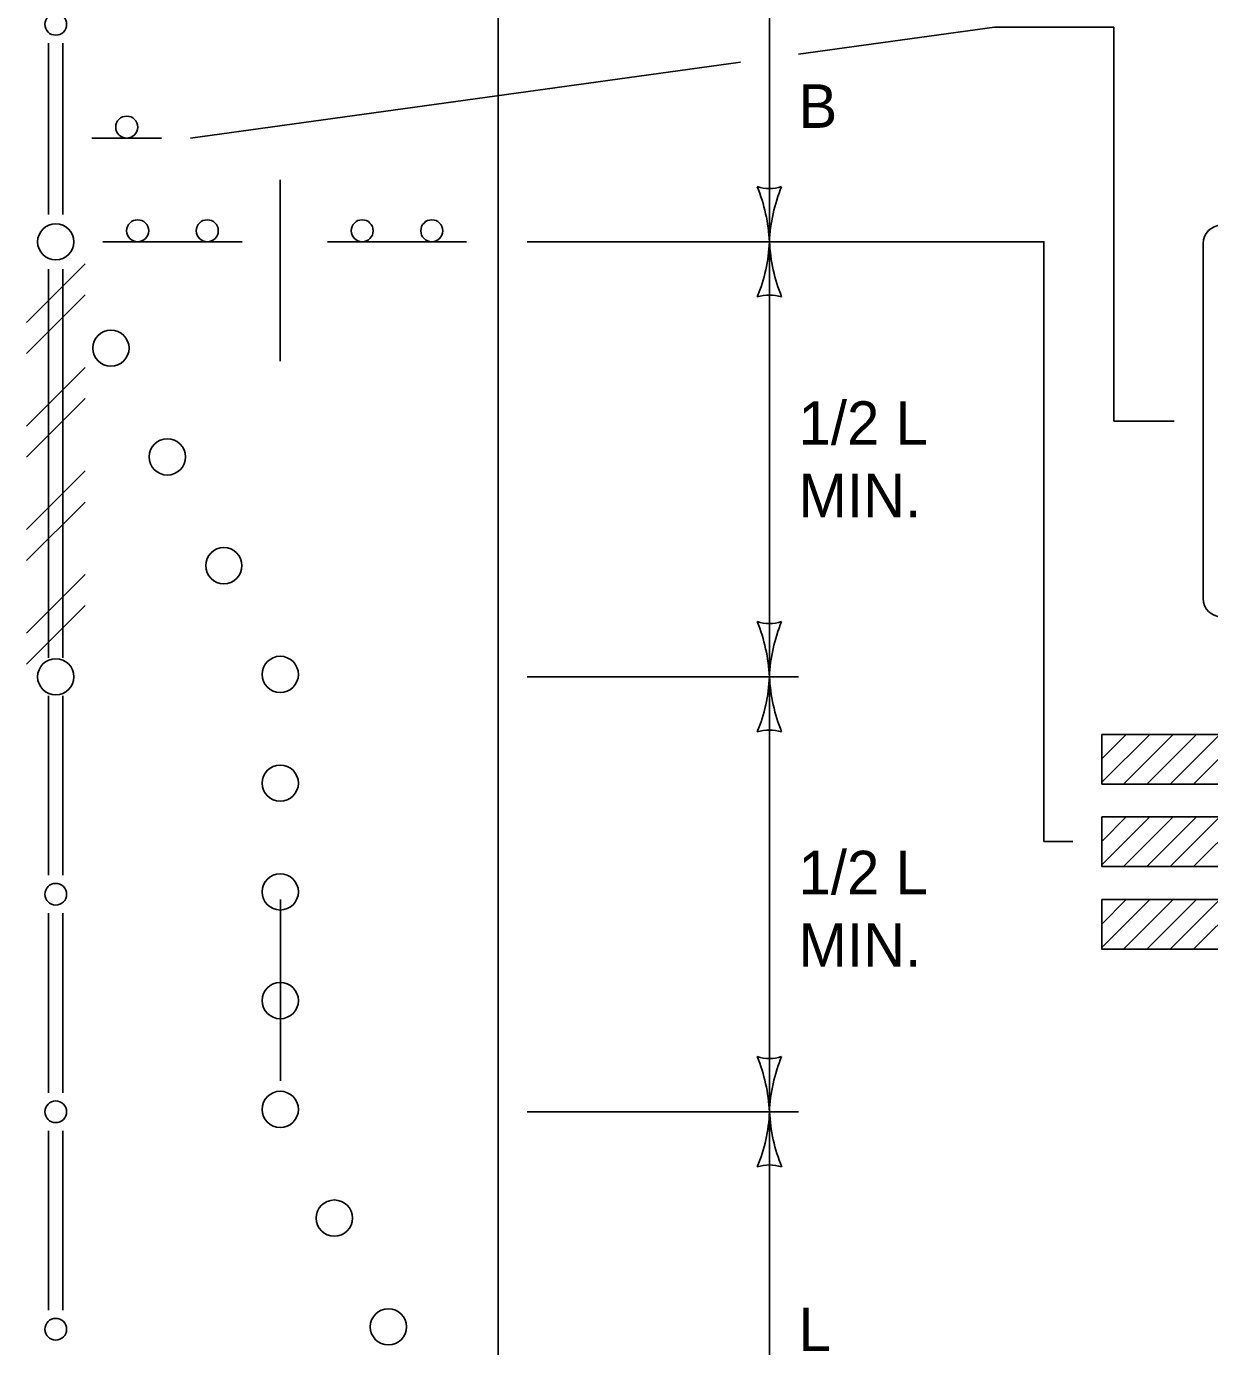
# Model space of a CAD drawing. Extents: x 49991.4 to 50021, y 49987.6 to 50011.4.
# Drawn here: x 50010.553 to 50012.184, y 49990.574 to 49992.395 of the extents above; entities that cross this region are included whole.
import ezdxf

# ---------------------------------------------------------------- set-up
doc = ezdxf.new("R2010")
doc.units = 0
for name, color, linetype in [('Level 1', 7, 'Continuous'), ('Level 2', 7, 'Continuous'), ('Level 3', 7, 'Continuous')]:
    doc.layers.add(name, color=color, linetype=linetype)

# ---------------------------------------------------------------- blocks, each defined once
blk = doc.blocks.new('ARR')
at = {"layer": 'Level 3'}
for centre, radius, start, end in [((1.53, 37.02), 37.05, 247.456, 267.6395), ((-21.37, 0), 9.13, 342.1388, 17.8612), ((1.92, -38.79), 38.83, 92.8273, 112.0772)]:
    blk.add_arc(centre, radius, start, end, dxfattribs=at)

msp = doc.modelspace()

# ---------------------------------------------------------------- linework, layer by layer
at = {"layer": 'Level 1'}
for p, q in [((50011.2032, 49988.1586), (50011.2032, 49992.9404)), ((50010.5832, 49992.1356), (50010.5832, 49992.3715)), ((50010.6032, 49992.1356), (50010.6032, 49992.3715)), ((50010.7392, 49992.2408), (50010.6432, 49992.2408)), ((50010.9028, 49991.9331), (50010.9028, 49992.1831)), ((50010.5682, 49992.0977), (50010.5682, 49992.0977)), ((50010.6582, 49992.0977), (50010.7542, 49992.0977)), ((50010.7542, 49992.0977), (50010.8502, 49992.0977)), ((50010.9678, 49992.0977), (50011.0638, 49992.0977)), ((50011.0638, 49992.0977), (50011.1598, 49992.0977)), ((50012.1754, 49991.6058), (50012.1754, 49992.0952)), ((50010.5528, 49991.9865), (50010.6336, 49992.0673)), ((50010.5832, 49991.5239), (50010.5832, 49992.0598)), ((50010.6032, 49991.5239), (50010.6032, 49992.0598)), ((50010.5528, 49991.9436), (50010.6336, 49992.0244)), ((50010.6443, 49991.951), (50010.6443, 49991.951)), ((50010.5528, 49991.8436), (50010.6336, 49991.9244)), ((50010.5528, 49991.8008), (50010.6336, 49991.8816)), ((50010.7222, 49991.801), (50010.7222, 49991.801)), ((50010.5528, 49991.7008), (50010.6336, 49991.7816)), ((50010.5528, 49991.6579), (50010.6336, 49991.7387)), ((50010.5528, 49991.5579), (50010.6336, 49991.6387)), ((50010.8, 49991.651), (50010.8, 49991.651)), ((50010.5528, 49991.5151), (50010.6336, 49991.5959)), ((50010.5682, 49991.4977), (50010.5682, 49991.4977)), ((50010.8778, 49991.501), (50010.8778, 49991.501)), ((50010.5832, 49991.2239), (50010.5832, 49991.4715)), ((50010.6032, 49991.2239), (50010.6032, 49991.4715)), ((50012.0359, 49991.3524), (50012.1018, 49991.4182)), ((50012.0359, 49991.3846), (50012.0695, 49991.4182)), ((50012.0695, 49991.4182), (50012.0359, 49991.3846)), ((50012.0359, 49991.3524), (50012.1018, 49991.4182)), ((50012.0656, 49991.3498), (50012.134, 49991.4182)), ((50012.134, 49991.4182), (50012.0656, 49991.3498)), ((50012.0978, 49991.3498), (50012.1662, 49991.4182)), ((50012.0978, 49991.3498), (50012.1662, 49991.4182)), ((50012.1301, 49991.3498), (50012.1985, 49991.4182)), ((50012.1985, 49991.4182), (50012.1301, 49991.3498)), ((50012.1623, 49991.3498), (50012.2307, 49991.4182)), ((50012.1623, 49991.3498), (50012.2307, 49991.4182)), ((50010.8778, 49991.351), (50010.8778, 49991.351)), ((50012.0359, 49991.2384), (50012.1018, 49991.3043)), ((50012.0359, 49991.2706), (50012.0695, 49991.3043)), ((50012.0695, 49991.3043), (50012.0359, 49991.2706)), ((50012.0359, 49991.2384), (50012.1018, 49991.3043)), ((50012.0656, 49991.2359), (50012.134, 49991.3043)), ((50012.134, 49991.3043), (50012.0656, 49991.2359)), ((50012.0978, 49991.2359), (50012.1662, 49991.3043)), ((50012.0978, 49991.2359), (50012.1662, 49991.3043)), ((50012.1301, 49991.2359), (50012.1985, 49991.3043)), ((50012.1985, 49991.3043), (50012.1301, 49991.2359)), ((50012.1623, 49991.2359), (50012.2307, 49991.3043)), ((50012.1623, 49991.2359), (50012.2307, 49991.3043)), ((50010.8778, 49991.201), (50010.8778, 49991.201)), ((50010.9033, 49990.9404), (50010.9033, 49991.1904)), ((50012.0359, 49991.1244), (50012.1018, 49991.1903)), ((50012.0359, 49991.1567), (50012.0695, 49991.1903)), ((50012.0695, 49991.1903), (50012.0359, 49991.1567)), ((50012.0359, 49991.1244), (50012.1018, 49991.1903)), ((50012.0656, 49991.1219), (50012.134, 49991.1903)), ((50012.134, 49991.1903), (50012.0656, 49991.1219)), ((50012.0978, 49991.1219), (50012.1662, 49991.1903)), ((50012.0978, 49991.1219), (50012.1662, 49991.1903)), ((50012.1301, 49991.1219), (50012.1985, 49991.1903)), ((50012.1985, 49991.1903), (50012.1301, 49991.1219)), ((50012.1623, 49991.1219), (50012.2307, 49991.1903)), ((50012.1623, 49991.1219), (50012.2307, 49991.1903)), ((50010.5832, 49990.9239), (50010.5832, 49991.1715)), ((50010.6032, 49990.9239), (50010.6032, 49991.1715)), ((50010.8778, 49991.051), (50010.8778, 49991.051)), ((50010.8778, 49990.901), (50010.8778, 49990.901)), ((50010.5832, 49990.6239), (50010.5832, 49990.8715)), ((50010.6032, 49990.6239), (50010.6032, 49990.8715))]:
    msp.add_line(p, q, dxfattribs=at)
for points in [[(50012.5147, 49991.3498), (50012.0359, 49991.3498), (50012.0359, 49991.4182), (50012.2411, 49991.4182)], [(50012.1018, 49991.4182), (50012.0695, 49991.4182)], [(50012.1662, 49991.4182), (50012.134, 49991.4182)], [(50012.0359, 49991.3846), (50012.0359, 49991.3524)], [(50012.0656, 49991.3498), (50012.0978, 49991.3498)], [(50012.1301, 49991.3498), (50012.1623, 49991.3498)], [(50012.5147, 49991.3043), (50012.7199, 49991.3043), (50012.7199, 49991.2359), (50012.0359, 49991.2359), (50012.0359, 49991.3043), (50012.5147, 49991.3043)], [(50012.1018, 49991.3043), (50012.0695, 49991.3043)], [(50012.1662, 49991.3043), (50012.134, 49991.3043)], [(50012.0359, 49991.2706), (50012.0359, 49991.2384)], [(50012.0656, 49991.2359), (50012.0978, 49991.2359)], [(50012.1301, 49991.2359), (50012.1623, 49991.2359)], [(50012.5531, 49991.1903), (50012.7199, 49991.1903), (50012.7199, 49991.1219), (50012.0359, 49991.1219), (50012.0359, 49991.1903), (50012.1985, 49991.1903)], [(50012.1018, 49991.1903), (50012.0695, 49991.1903)], [(50012.1662, 49991.1903), (50012.134, 49991.1903)], [(50012.0359, 49991.1567), (50012.0359, 49991.1244)], [(50012.0656, 49991.1219), (50012.0978, 49991.1219)], [(50012.1301, 49991.1219), (50012.1623, 49991.1219)]]:
    msp.add_lwpolyline(points, dxfattribs=at)
for centre, radius in [((50010.5932, 49992.3977), 0.015), ((50010.6911, 49992.2559), 0.0152), ((50010.5932, 49992.0977), 0.025), ((50010.7062, 49992.1129), 0.0152), ((50010.8022, 49992.1129), 0.0152), ((50011.0158, 49992.1129), 0.0152), ((50011.1118, 49992.1129), 0.0152), ((50010.6693, 49991.951), 0.025), ((50010.7471, 49991.801), 0.025), ((50010.825, 49991.651), 0.025), ((50010.5932, 49991.4977), 0.025), ((50010.9028, 49991.501), 0.025), ((50010.9028, 49991.351), 0.025), ((50010.9028, 49991.201), 0.025), ((50010.5932, 49991.1977), 0.015), ((50010.9028, 49991.051), 0.025), ((50010.5932, 49990.8977), 0.015), ((50010.9028, 49990.901), 0.025), ((50010.9774, 49990.751), 0.025), ((50011.0519, 49990.601), 0.025), ((50010.5932, 49990.5977), 0.015)]:
    msp.add_circle(centre, radius, dxfattribs=at)
for centre, radius, start, end in [((50010.5932, 49992.0977), 0.025, 0, 180), ((50012.2007, 49992.0952), 0.0253, 90, 180), ((50010.5932, 49992.0977), 0.025, 180, 0), ((50010.6693, 49991.951), 0.025, 0, 180), ((50010.6693, 49991.951), 0.025, 180, 0), ((50010.7471, 49991.801), 0.025, 0, 180), ((50010.7471, 49991.801), 0.025, 180, 0), ((50010.825, 49991.651), 0.025, 0, 180), ((50010.825, 49991.651), 0.025, 180, 0), ((50012.2007, 49991.6058), 0.0253, 180, 270), ((50010.5932, 49991.4977), 0.025, 0, 180), ((50010.9028, 49991.501), 0.025, 0, 180), ((50010.5932, 49991.4977), 0.025, 180, 0), ((50010.9028, 49991.501), 0.025, 180, 0), ((50010.9028, 49991.351), 0.025, 0, 180), ((50010.9028, 49991.351), 0.025, 180, 0), ((50010.9028, 49991.201), 0.025, 0, 180), ((50010.9028, 49991.201), 0.025, 180, 0), ((50010.9028, 49991.051), 0.025, 0, 180), ((50010.9028, 49991.051), 0.025, 180, 0), ((50010.9028, 49990.901), 0.025, 0, 180), ((50010.9028, 49990.901), 0.025, 180, 0), ((50010.9774, 49990.751), 0.025, 0, 180), ((50010.9774, 49990.751), 0.025, 180, 0), ((50011.0519, 49990.601), 0.025, 0, 180), ((50011.0519, 49990.601), 0.025, 180, 0)]:
    msp.add_arc(centre, radius, start, end, dxfattribs=at)
at = {"layer": 'Level 3'}
for p, q in [((50011.5774, 49992.0977), (50011.5774, 49992.4721)), ((50011.6174, 49992.3564), (50011.8876, 49992.3937)), ((50012.0525, 49992.3937), (50011.8876, 49992.3937)), ((50012.0525, 49992.2807), (50012.0525, 49992.3937)), ((50010.7792, 49992.2408), (50011.5374, 49992.3454)), ((50011.5774, 49992.0977), (50011.2432, 49992.0977)), ((50011.5774, 49991.4977), (50011.5774, 49992.0977)), ((50011.5774, 49992.0977), (50011.6174, 49992.0977)), ((50012.1354, 49991.8505), (50012.0525, 49991.8505)), ((50011.6174, 49991.4977), (50011.2432, 49991.4977)), ((50011.5774, 49990.8977), (50011.5774, 49991.4977)), ((50011.2432, 49990.8977), (50011.6174, 49990.8977)), ((50011.5774, 49990.2977), (50011.5774, 49990.8977))]:
    msp.add_line(p, q, dxfattribs=at)
for points in [[(50012.0525, 49992.2807), (50012.0525, 49991.8505)], [(50011.9959, 49991.2706), (50011.9559, 49991.2706), (50011.9559, 49992.0977), (50011.613, 49992.0977)]]:
    msp.add_lwpolyline(points, dxfattribs=at)
for centre, radius, start, end in [((50011.3553, 49990.9069), 0.2223, 337.456, 357.6395), ((50011.8102, 49990.9092), 0.233, 182.8273, 202.0772), ((50011.5774, 49990.7695), 0.0548, 72.1388, 107.8612)]:
    msp.add_arc(centre, radius, start, end, dxfattribs=at)

# ---------------------------------------------------------------- block references
at = {"layer": 'Level 3', "xscale": 0.006, "yscale": 0.006}
for p, rotation in [((50011.5774, 49992.0977), -90), ((50011.5774, 49992.0977), 90), ((50011.5774, 49991.4977), -90), ((50011.5774, 49991.4977), 90), ((50011.5774, 49990.8977), -90)]:
    msp.add_blockref('ARR', p, dxfattribs=dict(at, rotation=rotation))

# ---------------------------------------------------------------- texts
at = {"layer": 'Level 2'}
for s, p in [('B', (50011.6174, 49992.2549)), ('1/2 L', (50011.6174, 49991.8177)), ('MIN.', (50011.6174, 49991.7177)), ('1/2 L', (50011.6174, 49991.1977)), ('MIN.', (50011.6174, 49991.0977)), ('L', (50011.6174, 49990.5677))]:
    msp.add_text(s, height=0.06, dxfattribs=at).set_placement(p)

doc.saveas('drawing.dxf')
